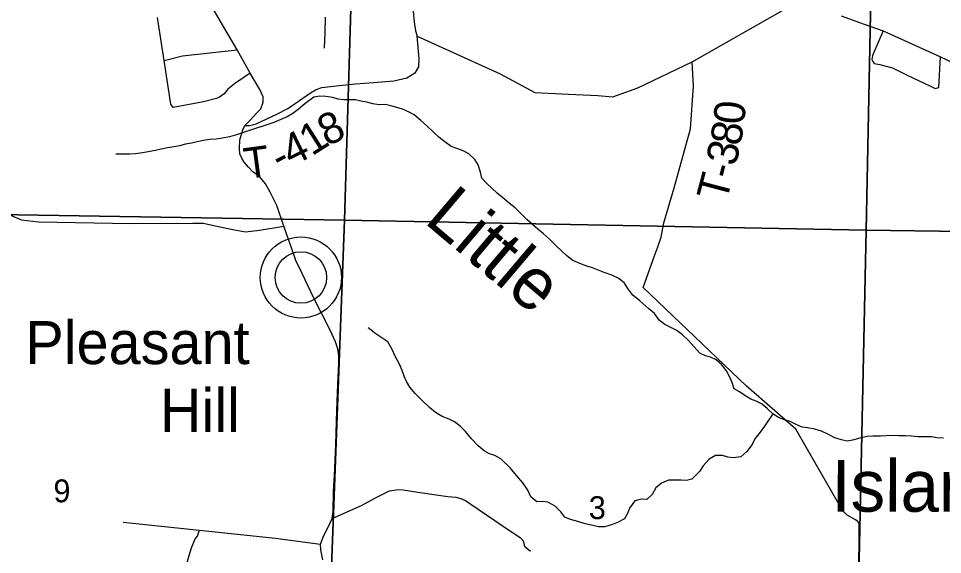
# Model space of a CAD drawing. Extents: x 2.1 to 8.9, y 14.1 to 20.9.
# Drawn here: x 4.863 to 6.556, y 15.459 to 16.441 of the extents above; entities that cross this region are included whole.
import ezdxf

# ---------------------------------------------------------------- set-up
doc = ezdxf.new("R2010")
doc.units = 0
for name, color, linetype in [('GM_X_City_Street', 7, 'Continuous'), ('GM_X_County_Road_Text', 7, 'Continuous'), ('GM_X_Interchange_Ramps', 7, 'Continuous'), ('GM_X_Major_River', 7, 'Continuous'), ('GM_X_Minor_River_Text', 7, 'Continuous'), ('GM_X_Rail_Line_Text', 7, 'Continuous'), ('GM_X_State_Route', 7, 'Continuous'), ('GM_X_State_Shield', 7, 'Continuous'), ('GM_X_Township_Text', 7, 'Continuous'), ('PV_P_Text', 7, 'Continuous'), ('TX_P_Misc', 7, 'Continuous')]:
    doc.layers.add(name, color=color, linetype=linetype)

msp = doc.modelspace()

# ---------------------------------------------------------------- linework, layer by layer
at = {"layer": 'GM_X_City_Street'}
for p, q in [((5.5735, 16.584), (5.5875, 16.4351)), ((6.097, 16.3616), (6.2708, 16.4605)), ((5.1293, 16.3639), (5.1173, 16.4432)), ((5.4248, 16.415), (5.4251, 16.4434)), ((6.3703, 16.4458), (6.4124, 16.4309)), ((5.5875, 16.4351), (5.5899, 16.4186)), ((6.4124, 16.4309), (6.4472, 16.4186)), ((5.4236, 16.387), (5.4248, 16.415)), ((5.5899, 16.4186), (5.5932, 16.4089)), ((5.5932, 16.4089), (5.7455, 16.3395)), ((5.5967, 16.3678), (5.5932, 16.4089)), ((6.4472, 16.4186), (6.4276, 16.3733)), ((6.4472, 16.4186), (6.5522, 16.3711)), ((5.1634, 16.3725), (5.2634, 16.3835)), ((6.4276, 16.3733), (6.4265, 16.3657)), ((5.1293, 16.3639), (5.1634, 16.3725)), ((5.1418, 16.2841), (5.1293, 16.3639)), ((5.5964, 16.3524), (5.5967, 16.3678)), ((5.9976, 16.314), (6.097, 16.3616)), ((6.0992, 16.3171), (6.097, 16.3616)), ((6.4265, 16.3657), (6.4282, 16.3623)), ((6.4282, 16.3623), (6.4308, 16.3588)), ((6.4308, 16.3588), (6.4411, 16.3566)), ((6.4411, 16.3566), (6.4641, 16.3507)), ((6.549, 16.3147), (6.5522, 16.3711)), ((6.5522, 16.3711), (6.5866, 16.3545)), ((5.2871, 16.3411), (5.2583, 16.3215)), ((5.5744, 16.3325), (5.5901, 16.3419)), ((5.5901, 16.3419), (5.5964, 16.3524)), ((5.7455, 16.3395), (5.8089, 16.3058)), ((6.4641, 16.3507), (6.4897, 16.3378)), ((5.4804, 16.3217), (5.5133, 16.3238)), ((5.5133, 16.3238), (5.5503, 16.3271)), ((5.5503, 16.3271), (5.5744, 16.3325)), ((6.4897, 16.3378), (6.534, 16.3174)), ((5.246, 16.3118), (5.2392, 16.3032)), ((5.2583, 16.3215), (5.246, 16.3118)), ((5.3979, 16.3051), (5.4083, 16.3108)), ((5.4083, 16.3108), (5.4186, 16.3144)), ((5.4186, 16.3144), (5.4503, 16.3182)), ((5.4503, 16.3182), (5.4804, 16.3217)), ((5.8089, 16.3058), (5.8707, 16.3024)), ((5.9519, 16.2974), (5.9976, 16.314)), ((6.0937, 16.2387), (6.0992, 16.3171)), ((6.534, 16.3174), (6.5423, 16.3131)), ((6.5423, 16.3131), (6.549, 16.3147)), ((5.2016, 16.2887), (5.1462, 16.2778)), ((5.2257, 16.2946), (5.2016, 16.2887)), ((5.2312, 16.2972), (5.2257, 16.2946)), ((5.2392, 16.3032), (5.2312, 16.2972)), ((5.3564, 16.2759), (5.3777, 16.2907)), ((5.3777, 16.2907), (5.3979, 16.3051)), ((5.8707, 16.3024), (5.924, 16.2998)), ((5.924, 16.2998), (5.9519, 16.2974)), ((5.1462, 16.2778), (5.1418, 16.2841)), ((5.3358, 16.2657), (5.3564, 16.2759)), ((5.2979, 16.248), (5.3358, 16.2657)), ((5.2771, 16.2448), (5.2858, 16.2452)), ((5.2858, 16.2452), (5.2979, 16.248)), ((6.0638, 16.1306), (6.0937, 16.2387)), ((6.0451, 16.0667), (6.0638, 16.1306)), ((6.0404, 16.0401), (6.0451, 16.0667)), ((6.034, 16.0228), (6.0404, 16.0401)), ((6.0285, 16.0077), (6.034, 16.0228)), ((6.0071, 15.9482), (6.028, 16.0064)), ((6.028, 16.0064), (6.0285, 16.0077)), ((6.1959, 15.7676), (6.0071, 15.9482)), ((6.2869, 15.6882), (6.1959, 15.7676)), ((6.3693, 15.545), (6.2869, 15.6882)), ((5.5422, 15.5752), (5.5588, 15.578)), ((5.5588, 15.578), (5.5675, 15.5773)), ((5.5675, 15.5773), (5.5946, 15.5732)), ((5.4914, 15.5485), (5.5166, 15.5628)), ((5.5166, 15.5628), (5.5422, 15.5752)), ((5.5946, 15.5732), (5.6495, 15.5653)), ((5.6495, 15.5653), (5.6642, 15.5639)), ((5.6642, 15.5639), (5.6734, 15.5614)), ((5.6734, 15.5614), (5.6814, 15.5578)), ((5.4371, 15.5248), (5.4914, 15.5485)), ((5.6814, 15.5578), (5.6915, 15.551)), ((5.6915, 15.551), (5.7643, 15.5014)), ((6.3748, 15.5367), (6.3693, 15.545)), ((6.3811, 15.5307), (6.3748, 15.5367)), ((6.3965, 15.5221), (6.3811, 15.5307)), ((5.0547, 15.5177), (5.3337, 15.4884)), ((6.4004, 15.5191), (6.3965, 15.5221)), ((6.403, 15.5146), (6.4004, 15.5191)), ((6.4031, 15.5071), (6.403, 15.5146)), ((5.7643, 15.5014), (5.7761, 15.4937)), ((5.7761, 15.4937), (5.7824, 15.4892)), ((6.4023, 15.4071), (6.4031, 15.5071)), ((5.3337, 15.4884), (5.3378, 15.488)), ((5.3378, 15.488), (5.4157, 15.4778)), ((5.7824, 15.4892), (5.7853, 15.4864)), ((5.7853, 15.4864), (5.7868, 15.485)), ((5.7868, 15.485), (5.7882, 15.481)), ((5.7882, 15.481), (5.789, 15.4769)), ((5.789, 15.4769), (5.7894, 15.4744)), ((5.7894, 15.4744), (5.7909, 15.4727)), ((5.7909, 15.4727), (5.8007, 15.465))]:
    msp.add_line(p, q, dxfattribs=at)
at = {"layer": 'GM_X_Interchange_Ramps'}
for p, q in [((5.492, 17.1117), (5.4597, 16.0717)), ((5.4597, 16.0717), (5.492, 17.1117)), ((6.4161, 16.0534), (6.4366, 17.1114)), ((6.4366, 17.1114), (6.4161, 16.0534)), ((5.4597, 16.0717), (4.4591, 16.088)), ((4.4591, 16.088), (5.4597, 16.0717)), ((5.4597, 16.0717), (5.4229, 15.0756)), ((5.4229, 15.0756), (5.4597, 16.0717)), ((6.4161, 16.0534), (5.4597, 16.0717)), ((5.4597, 16.0717), (6.4161, 16.0534)), ((6.4161, 16.0534), (6.3944, 15.0386)), ((6.3944, 15.0386), (6.4161, 16.0534)), ((7.438, 16.0393), (6.4161, 16.0534)), ((6.4161, 16.0534), (7.438, 16.0393))]:
    msp.add_line(p, q, dxfattribs=at)
at = {"layer": 'GM_X_Rail_Line_Text'}
for p, q in [((5.2634, 16.3835), (5.2031, 16.4864)), ((5.2871, 16.3411), (5.2634, 16.3835)), ((5.3047, 16.3112), (5.2871, 16.3411)), ((5.3107, 16.2975), (5.3047, 16.3112)), ((5.3112, 16.2877), (5.3107, 16.2975)), ((5.2982, 16.2669), (5.3066, 16.2757)), ((5.3066, 16.2757), (5.3112, 16.2877)), ((5.2771, 16.2448), (5.2881, 16.2558)), ((5.2881, 16.2558), (5.2982, 16.2669)), ((5.2736, 16.2371), (5.2771, 16.2448)), ((5.2684, 16.2187), (5.2736, 16.2371)), ((5.2673, 16.2031), (5.2684, 16.2187)), ((5.2684, 16.1933), (5.2673, 16.2031)), ((5.2718, 16.1854), (5.2684, 16.1933)), ((5.2761, 16.1777), (5.2718, 16.1854)), ((5.2841, 16.1688), (5.2761, 16.1777)), ((5.2923, 16.1604), (5.2841, 16.1688)), ((5.3045, 16.1518), (5.2923, 16.1604)), ((5.3153, 16.1383), (5.3045, 16.1518)), ((5.3236, 16.1228), (5.3153, 16.1383)), ((5.3357, 16.0984), (5.3236, 16.1228)), ((5.3491, 16.0608), (5.3357, 16.0984)), ((5.359, 16.0313), (5.3491, 16.0608)), ((5.3708, 15.9975), (5.359, 16.0313)), ((5.3822, 15.9735), (5.3708, 15.9975)), ((5.4036, 15.9288), (5.3822, 15.9735)), ((5.4333, 15.8712), (5.4036, 15.9288)), ((5.4433, 15.8485), (5.4333, 15.8712)), ((5.4475, 15.8354), (5.4433, 15.8485)), ((5.4496, 15.8227), (5.4475, 15.8354)), ((5.4496, 15.8088), (5.4496, 15.8227)), ((5.4478, 15.7712), (5.4496, 15.8088)), ((5.446, 15.7231), (5.4478, 15.7712)), ((5.4448, 15.6817), (5.446, 15.7231)), ((5.4439, 15.6599), (5.4448, 15.6817)), ((5.4414, 15.6036), (5.4439, 15.6599)), ((5.4398, 15.5748), (5.4414, 15.6036)), ((5.4391, 15.5373), (5.4398, 15.5748)), ((5.4371, 15.5248), (5.4391, 15.5373)), ((5.4302, 15.5087), (5.4371, 15.5248)), ((5.4157, 15.4778), (5.4223, 15.4933)), ((5.4223, 15.4933), (5.4302, 15.5087)), ((5.4164, 15.4673), (5.4157, 15.4778)), ((5.4204, 15.4489), (5.4164, 15.4673))]:
    msp.add_line(p, q, dxfattribs=at)
at = {"layer": 'GM_X_State_Route'}
for radius in [0.0744, 0.0472]:
    msp.add_circle((5.3801, 15.9664), radius, dxfattribs=at)
at = {"layer": 'GM_X_State_Shield'}
for p, q in [((4.8482, 16.0809), (4.8683, 16.0722)), ((4.8683, 16.0722), (4.899, 16.0682)), ((4.899, 16.0682), (5.0689, 16.0652)), ((5.0689, 16.0652), (5.182, 16.0663)), ((5.182, 16.0663), (5.201, 16.0659)), ((5.201, 16.0659), (5.2377, 16.0581)), ((5.2377, 16.0581), (5.2586, 16.0538)), ((5.2586, 16.0538), (5.2785, 16.0501)), ((5.2785, 16.0501), (5.3045, 16.0533)), ((5.3045, 16.0533), (5.3491, 16.0608))]:
    msp.add_line(p, q, dxfattribs=at)
at = {"layer": 'GM_X_Township_Text'}
msp.add_line((5.3801, 15.9664), (5.3801, 15.9664), dxfattribs=at)
at = {"layer": 'TX_P_Misc'}
for p, q in [((5.4039, 16.2971), (5.3872, 16.2847)), ((5.4145, 16.2985), (5.4039, 16.2971)), ((5.4259, 16.2981), (5.4145, 16.2985)), ((5.4389, 16.2963), (5.4259, 16.2981)), ((5.4485, 16.2935), (5.4389, 16.2963)), ((5.4588, 16.2919), (5.4485, 16.2935)), ((5.4687, 16.2922), (5.4588, 16.2919)), ((5.4801, 16.2918), (5.4687, 16.2922)), ((5.4901, 16.2898), (5.4801, 16.2918)), ((5.5012, 16.2875), (5.4901, 16.2898)), ((5.375, 16.2741), (5.3653, 16.2669)), ((5.3872, 16.2847), (5.375, 16.2741)), ((5.5119, 16.2848), (5.5012, 16.2875)), ((5.5237, 16.2829), (5.5119, 16.2848)), ((5.5351, 16.2833), (5.5237, 16.2829)), ((5.5447, 16.2809), (5.5351, 16.2833)), ((5.5558, 16.2782), (5.5447, 16.2809)), ((5.5665, 16.2751), (5.5558, 16.2782)), ((5.5773, 16.2701), (5.5665, 16.2751)), ((5.3436, 16.256), (5.3305, 16.2506)), ((5.3549, 16.2609), (5.3436, 16.256)), ((5.3653, 16.2669), (5.3549, 16.2609)), ((5.5874, 16.2643), (5.5773, 16.2701)), ((5.5999, 16.2544), (5.5874, 16.2643)), ((5.6104, 16.2453), (5.5999, 16.2544)), ((5.2985, 16.2401), (5.2876, 16.2367)), ((5.3083, 16.2431), (5.2985, 16.2401)), ((5.3196, 16.2469), (5.3083, 16.2431)), ((5.3305, 16.2506), (5.3196, 16.2469)), ((5.623, 16.2331), (5.6104, 16.2453)), ((5.2367, 16.2218), (5.2246, 16.2199)), ((5.2492, 16.2245), (5.2367, 16.2218)), ((5.262, 16.2279), (5.2492, 16.2245)), ((5.2748, 16.2325), (5.262, 16.2279)), ((5.2876, 16.2367), (5.2748, 16.2325)), ((5.6331, 16.2239), (5.623, 16.2331)), ((5.6437, 16.2151), (5.6331, 16.2239)), ((5.1358, 16.2039), (5.124, 16.2016)), ((5.1479, 16.2061), (5.1358, 16.2039)), ((5.1577, 16.208), (5.1479, 16.2061)), ((5.1686, 16.2106), (5.1577, 16.208)), ((5.1796, 16.2128), (5.1686, 16.2106)), ((5.1902, 16.2151), (5.1796, 16.2128)), ((5.2015, 16.2177), (5.1902, 16.2151)), ((5.2125, 16.2192), (5.2015, 16.2177)), ((5.2246, 16.2199), (5.2125, 16.2192)), ((5.6557, 16.2067), (5.6437, 16.2151)), ((5.6657, 16.2028), (5.6557, 16.2067)), ((5.0433, 16.1926), (5.0411, 16.1925)), ((5.0532, 16.1925), (5.0433, 16.1926)), ((5.0658, 16.1922), (5.0532, 16.1925)), ((5.0772, 16.1929), (5.0658, 16.1922)), ((5.09, 16.1948), (5.0772, 16.1929)), ((5.1139, 16.199), (5.09, 16.1948)), ((5.124, 16.2016), (5.1139, 16.199)), ((5.6773, 16.1986), (5.6657, 16.2028)), ((5.6881, 16.1929), (5.6773, 16.1986)), ((5.699, 16.1829), (5.6881, 16.1929)), ((5.705, 16.1729), (5.699, 16.1829)), ((5.7093, 16.1593), (5.705, 16.1729)), ((5.7119, 16.1483), (5.7093, 16.1593)), ((5.7209, 16.1387), (5.7119, 16.1483)), ((5.7397, 16.121), (5.7209, 16.1387)), ((5.7499, 16.1126), (5.7397, 16.121)), ((5.762, 16.1027), (5.7499, 16.1126)), ((5.7729, 16.0943), (5.762, 16.1027)), ((5.7831, 16.0836), (5.7729, 16.0943)), ((5.7941, 16.0729), (5.7831, 16.0836)), ((5.8144, 16.0553), (5.7941, 16.0729)), ((5.8249, 16.0465), (5.8144, 16.0553)), ((5.8359, 16.0365), (5.8249, 16.0465)), ((5.8472, 16.0251), (5.8359, 16.0365)), ((5.8574, 16.0151), (5.8472, 16.0251)), ((5.8672, 16.0059), (5.8574, 16.0151)), ((5.8785, 15.9975), (5.8672, 16.0059)), ((5.8912, 15.9918), (5.8785, 15.9975)), ((5.9043, 15.9873), (5.8912, 15.9918)), ((5.9143, 15.9842), (5.9043, 15.9873)), ((5.9358, 15.9757), (5.9143, 15.9842)), ((5.9501, 15.9705), (5.9358, 15.9757)), ((5.9624, 15.9644), (5.9501, 15.9705)), ((5.973, 15.956), (5.9624, 15.9644)), ((5.9793, 15.9463), (5.973, 15.956)), ((5.9881, 15.934), (5.9793, 15.9463)), ((6.0013, 15.9234), (5.9881, 15.934)), ((6.0178, 15.909), (6.0013, 15.9234)), ((6.0279, 15.9006), (6.0178, 15.909)), ((6.037, 15.8876), (6.0279, 15.9006)), ((6.0472, 15.8803), (6.037, 15.8876)), ((5.506, 15.8725), (5.5033, 15.874)), ((5.5158, 15.8641), (5.506, 15.8725)), ((6.0568, 15.8753), (6.0472, 15.8803)), ((6.0676, 15.8699), (6.0568, 15.8753)), ((6.0785, 15.8622), (6.0676, 15.8699)), ((5.5282, 15.8561), (5.5158, 15.8641)), ((5.5391, 15.8485), (5.5282, 15.8561)), ((5.5467, 15.8354), (5.5391, 15.8485)), ((6.0903, 15.8512), (6.0785, 15.8622)), ((6.1005, 15.8393), (6.0903, 15.8512)), ((5.5536, 15.8211), (5.5467, 15.8354)), ((6.1112, 15.8275), (6.1005, 15.8393)), ((5.5609, 15.8073), (5.5536, 15.8211)), ((6.1212, 15.8229), (6.1112, 15.8275)), ((6.1308, 15.8201), (6.1212, 15.8229)), ((6.1408, 15.8155), (6.1308, 15.8201)), ((6.1506, 15.8071), (6.1408, 15.8155)), ((5.5658, 15.796), (5.5609, 15.8073)), ((6.1601, 15.7952), (6.1506, 15.8071)), ((5.5696, 15.7855), (5.5658, 15.796)), ((5.5737, 15.7757), (5.5696, 15.7855)), ((6.1657, 15.7847), (6.1601, 15.7952)), ((6.1702, 15.7738), (6.1657, 15.7847)), ((5.5797, 15.7656), (5.5737, 15.7757)), ((5.5896, 15.7538), (5.5797, 15.7656)), ((6.174, 15.7621), (6.1702, 15.7738)), ((5.6021, 15.7412), (5.5896, 15.7538)), ((6.1837, 15.7567), (6.174, 15.7621)), ((6.1938, 15.7502), (6.1837, 15.7567)), ((6.2046, 15.7437), (6.1938, 15.7502)), ((5.6158, 15.7284), (5.6021, 15.7412)), ((6.2146, 15.7395), (6.2046, 15.7437)), ((6.2251, 15.7341), (6.2146, 15.7395)), ((6.2348, 15.7256), (6.2251, 15.7341)), ((5.6268, 15.7188), (5.6158, 15.7284)), ((5.6388, 15.7116), (5.6268, 15.7188)), ((6.2446, 15.7168), (6.2298, 15.6939)), ((6.2446, 15.7168), (6.2348, 15.7256)), ((6.2555, 15.7099), (6.2446, 15.7168)), ((5.6515, 15.7066), (5.6388, 15.7116)), ((5.6615, 15.702), (5.6515, 15.7066)), ((5.6717, 15.694), (5.6615, 15.702)), ((6.2663, 15.7053), (6.2555, 15.7099)), ((6.2766, 15.7022), (6.2663, 15.7053)), ((6.289, 15.6965), (6.2766, 15.7022)), ((6.2986, 15.6923), (6.289, 15.6965)), ((5.6819, 15.684), (5.6717, 15.694)), ((5.6929, 15.671), (5.6819, 15.684)), ((6.2217, 15.683), (6.2119, 15.6705)), ((6.2298, 15.6939), (6.2217, 15.683)), ((6.3089, 15.6907), (6.2986, 15.6923)), ((6.3219, 15.6884), (6.3089, 15.6907)), ((6.3338, 15.685), (6.3219, 15.6884)), ((6.3466, 15.6785), (6.3338, 15.685)), ((5.7047, 15.6577), (5.6929, 15.671)), ((6.2119, 15.6705), (6.2072, 15.6605)), ((6.3585, 15.6728), (6.3466, 15.6785)), ((6.3704, 15.669), (6.3585, 15.6728)), ((6.3808, 15.6667), (6.3704, 15.669)), ((6.391, 15.6681), (6.3808, 15.6667)), ((6.4042, 15.672), (6.391, 15.6681)), ((6.4178, 15.6751), (6.4042, 15.672)), ((6.4284, 15.6758), (6.4178, 15.6751)), ((6.4421, 15.6758), (6.4284, 15.6758)), ((6.4523, 15.6765), (6.4421, 15.6758)), ((6.4637, 15.6769), (6.4523, 15.6765)), ((6.4755, 15.6765), (6.4637, 15.6769)), ((6.4877, 15.6761), (6.4755, 15.6765)), ((6.4987, 15.6753), (6.4877, 15.6761)), ((6.5113, 15.6746), (6.4987, 15.6753)), ((6.5246, 15.6746), (6.5113, 15.6746)), ((6.5357, 15.6742), (6.5246, 15.6746)), ((6.5456, 15.6726), (6.5357, 15.6742)), ((6.5574, 15.6718), (6.5456, 15.6726)), ((5.7157, 15.6485), (5.7047, 15.6577)), ((5.7257, 15.6435), (5.7157, 15.6485)), ((6.1974, 15.6472), (6.1863, 15.6378)), ((6.2072, 15.6605), (6.1974, 15.6472)), ((5.7353, 15.64), (5.7257, 15.6435)), ((5.7465, 15.6343), (5.7353, 15.64)), ((5.7638, 15.6173), (5.7465, 15.6343)), ((6.1282, 15.6337), (6.1172, 15.6215)), ((6.1398, 15.6401), (6.1282, 15.6337)), ((6.1524, 15.6401), (6.1398, 15.6401)), ((6.1623, 15.6374), (6.1524, 15.6401)), ((6.1726, 15.6358), (6.1623, 15.6374)), ((6.1863, 15.6378), (6.1726, 15.6358)), ((5.7752, 15.6036), (5.7638, 15.6173)), ((6.1107, 15.6111), (6.0967, 15.5969)), ((6.1172, 15.6215), (6.1107, 15.6111)), ((5.7867, 15.5903), (5.7752, 15.6036)), ((6.0534, 15.5948), (6.0406, 15.5895)), ((6.0648, 15.5952), (6.0534, 15.5948)), ((6.0766, 15.5948), (6.0648, 15.5952)), ((6.0869, 15.5943), (6.0766, 15.5948)), ((6.0967, 15.5969), (6.0869, 15.5943)), ((5.7958, 15.5769), (5.7867, 15.5903)), ((6.0307, 15.5808), (6.0238, 15.5684)), ((6.0406, 15.5895), (6.0307, 15.5808)), ((5.8015, 15.5645), (5.7958, 15.5769)), ((5.8125, 15.555), (5.8015, 15.5645)), ((6.0238, 15.5684), (6.0138, 15.5594)), ((5.8227, 15.5557), (5.8125, 15.555)), ((5.8326, 15.5548), (5.8227, 15.5557)), ((5.8462, 15.5473), (5.8326, 15.5548)), ((5.8564, 15.5369), (5.8462, 15.5473)), ((5.982, 15.5435), (5.9785, 15.5339)), ((5.9922, 15.5572), (5.982, 15.5435)), ((6.0035, 15.5602), (5.9922, 15.5572)), ((6.0138, 15.5594), (6.0035, 15.5602)), ((5.8635, 15.5269), (5.8564, 15.5369)), ((5.8743, 15.5227), (5.8635, 15.5269)), ((5.9785, 15.5339), (5.9731, 15.5242)), ((5.8877, 15.5193), (5.8743, 15.5227)), ((5.9008, 15.5151), (5.8877, 15.5193)), ((5.9123, 15.5124), (5.9008, 15.5151)), ((5.9257, 15.5094), (5.9123, 15.5124)), ((5.9363, 15.5094), (5.9257, 15.5094)), ((5.9495, 15.5132), (5.9363, 15.5094)), ((5.9612, 15.5178), (5.9495, 15.5132)), ((5.9731, 15.5242), (5.9612, 15.5178)), ((5.1906, 15.4923), (5.1934, 15.5018)), ((5.1796, 15.4712), (5.1865, 15.4873)), ((5.1865, 15.4873), (5.1906, 15.4923)), ((5.1696, 15.4387), (5.1796, 15.4712))]:
    msp.add_line(p, q, dxfattribs=at)

# ---------------------------------------------------------------- texts
at = {"layer": 'GM_X_County_Road_Text'}
for s, p in [('9', (4.9267, 15.5544)), ('3', (5.9076, 15.5236))]:
    msp.add_text(s, height=0.0419, rotation=0, dxfattribs=at).set_placement(p)
at = {"layer": 'GM_X_Major_River'}
for s, p in [('Pleasant', (4.8751, 15.8076)), ('Hill', (5.1217, 15.6835))]:
    msp.add_text(s, height=0.07898, rotation=0, dxfattribs=at).set_placement(p)
at = {"layer": 'GM_X_Minor_River_Text'}
for s, rotation, p in [('0', 84.7164, (6.1921, 16.2456)), ('8', 25.7086, (5.428, 16.206)), ('1', 32.3771, (5.4, 16.1881)), ('8', 79.7101, (6.1851, 16.2058)), ('4', 25.9343, (5.3624, 16.1694)), ('T', 7.6252, (5.2795, 16.1467)), ('3', 77.0167, (6.1767, 16.1688)), ('-', 27.5351, (5.3421, 16.1588)), ('-', 75.6099, (6.1705, 16.1448)), ('T', 75.1914, (6.1595, 16.1032))]:
    msp.add_text(s, height=0.0568, rotation=rotation, dxfattribs=at).set_placement(p)
at = {"layer": 'PV_P_Text'}
for s, height, rotation, p in [('Little', 0.09472, 319.7029, (5.6036, 16.0685)), ('Island', 0.0947, 359.8692, (6.3521, 15.5374))]:
    msp.add_text(s, height=height, rotation=rotation, dxfattribs=at).set_placement(p)

doc.saveas('drawing.dxf')
